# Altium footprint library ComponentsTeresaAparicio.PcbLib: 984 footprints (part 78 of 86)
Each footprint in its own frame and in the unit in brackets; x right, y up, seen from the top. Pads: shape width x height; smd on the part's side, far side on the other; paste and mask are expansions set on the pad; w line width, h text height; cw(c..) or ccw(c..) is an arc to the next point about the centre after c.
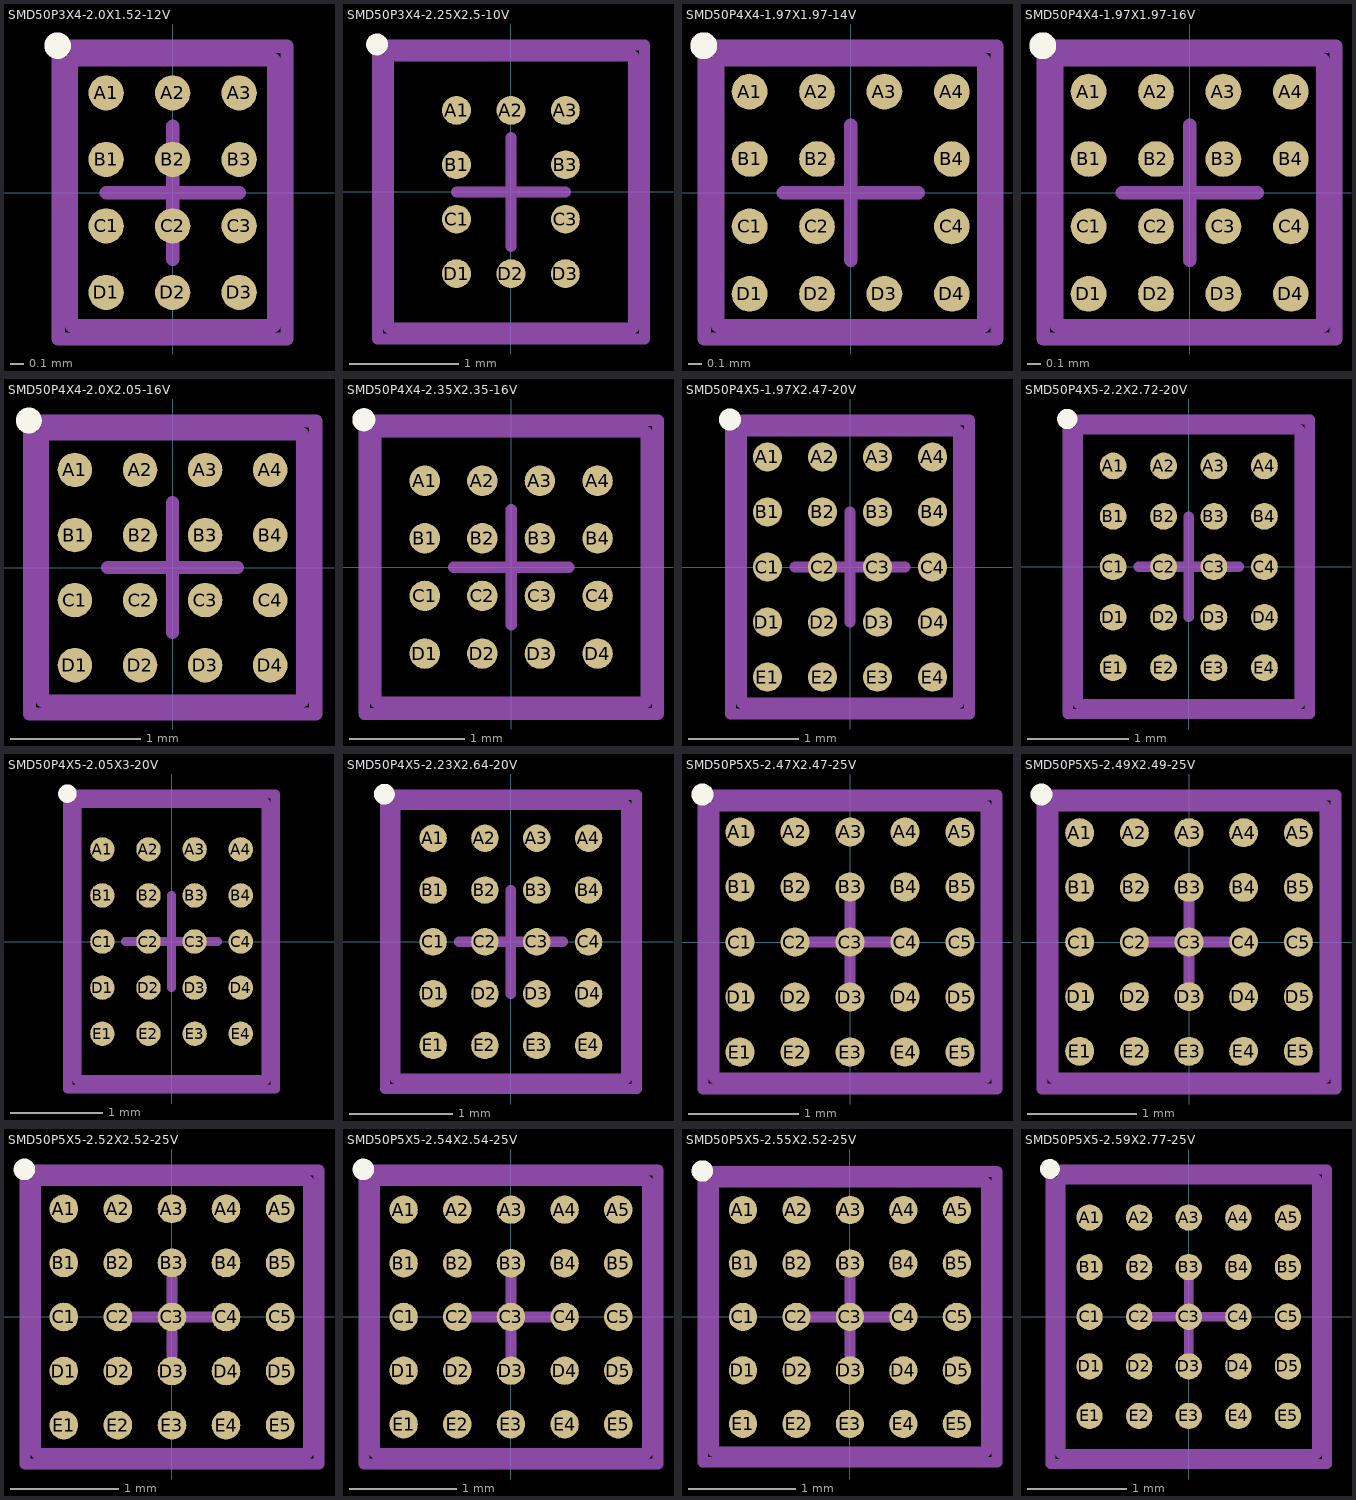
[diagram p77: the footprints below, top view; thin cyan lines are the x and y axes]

## SMD50P3X4-2.0X1.52-12V [mm] "Micro SMD, 12-Leads, Body 1.52x2.0mm, Pitch 0.5mm, NSC Recommended"
height 0.68
pads (12):
  round 0.265 smd paste-0.132 mask+0.05: A1(-0.5,0.75) A2(0,0.75) A3(0.5,0.75) B1(-0.5,0.25) B2(0,0.25) B3(0.5,0.25) C1(-0.5,-0.25) C2(0,-0.25) C3(0.5,-0.25) D1(-0.5,-0.75) D2(0,-0.75) D3(0.5,-0.75)
Top Overlay:
  circle w0.1: c-0.865,1.105 r0.05
Top Paste:
  circle w0.05: c0.075,-0.7 r0.025
  circle w0.05: c-0.075,-0.85 r0.025
  circle w0.05: c-0.075,-0.7 r0.025
  circle w0.05: c0.075,-0.85 r0.025
  circle w0.05: c-0.45,0.175 r0.025
  circle w0.05: c-0.6,0.325 r0.025
  circle w0.05: c-0.6,0.175 r0.025
  circle w0.05: c-0.45,0.325 r0.025
  circle w0.05: c-0.45,-0.325 r0.025
  circle w0.05: c-0.6,-0.175 r0.025
  circle w0.05: c-0.6,-0.325 r0.025
  circle w0.05: c-0.45,-0.175 r0.025
  circle w0.05: c0.075,0.7 r0.025
  circle w0.05: c-0.075,0.85 r0.025
  circle w0.05: c-0.075,0.7 r0.025
  circle w0.05: c0.075,0.85 r0.025
  circle w0.05: c0.6,-0.325 r0.025
  circle w0.05: c0.45,-0.175 r0.025
  circle w0.05: c0.45,-0.325 r0.025
  circle w0.05: c0.6,-0.175 r0.025
  circle w0.05: c0.6,0.175 r0.025
  circle w0.05: c0.45,0.325 r0.025
  circle w0.05: c0.45,0.175 r0.025
  circle w0.05: c0.6,0.325 r0.025
  circle w0.05: c0.075,0.325 r0.025
  circle w0.05: c-0.075,0.175 r0.025
  circle w0.05: c-0.075,0.325 r0.025
  circle w0.05: c0.075,0.175 r0.025
  circle w0.05: c0.075,-0.175 r0.025
  circle w0.05: c-0.075,-0.325 r0.025
  circle w0.05: c-0.075,-0.175 r0.025
  circle w0.05: c0.075,-0.325 r0.025
  circle w0.05: c-0.45,0.7 r0.025
  circle w0.05: c-0.6,0.85 r0.025
  circle w0.05: c-0.6,0.7 r0.025
  circle w0.05: c-0.45,0.85 r0.025
  circle w0.05: c0.6,0.7 r0.025
  circle w0.05: c0.45,0.85 r0.025
  circle w0.05: c0.45,0.7 r0.025
  circle w0.05: c0.6,0.85 r0.025
  circle w0.05: c-0.45,-0.7 r0.025
  circle w0.05: c-0.6,-0.85 r0.025
  circle w0.05: c-0.6,-0.7 r0.025
  circle w0.05: c-0.45,-0.85 r0.025
  circle w0.05: c0.6,-0.7 r0.025
  circle w0.05: c0.45,-0.85 r0.025
  circle w0.05: c0.45,-0.7 r0.025
  circle w0.05: c0.6,-0.85 r0.025
  rectangle: -0.075,-0.9 0.075,-0.85
  region: -0.125,-0.7 -0.125,-0.85 -0.075,-0.85 -0.075,-0.7
  region: 0.075,-0.65 -0.075,-0.65 -0.075,-0.7 0.075,-0.7
  region: 0.125,-0.85 0.125,-0.7 0.075,-0.7 0.075,-0.85
  region: -0.075,-0.7 -0.075,-0.85 0.075,-0.85 0.075,-0.7
  region: -0.6,0.325 -0.6,0.175 -0.45,0.175 -0.45,0.325
  region: -0.4,0.175 -0.4,0.325 -0.45,0.325 -0.45,0.175
  region: -0.45,0.375 -0.6,0.375 -0.6,0.325 -0.45,0.325
  region: -0.65,0.325 -0.65,0.175 -0.6,0.175 -0.6,0.325
  rectangle: -0.6,0.125 -0.45,0.175
  region: -0.6,-0.175 -0.6,-0.325 -0.45,-0.325 -0.45,-0.175
  region: -0.4,-0.325 -0.4,-0.175 -0.45,-0.175 -0.45,-0.325
  region: -0.45,-0.125 -0.6,-0.125 -0.6,-0.175 -0.45,-0.175
  region: -0.65,-0.175 -0.65,-0.325 -0.6,-0.325 -0.6,-0.175
  rectangle: -0.6,-0.375 -0.45,-0.325
  region: -0.075,0.85 -0.075,0.7 0.075,0.7 0.075,0.85
  region: 0.125,0.7 0.125,0.85 0.075,0.85 0.075,0.7
  region: 0.075,0.9 -0.075,0.9 -0.075,0.85 0.075,0.85
  region: -0.125,0.85 -0.125,0.7 -0.075,0.7 -0.075,0.85
  rectangle: -0.075,0.65 0.075,0.7
  region: 0.45,-0.175 0.45,-0.325 0.6,-0.325 0.6,-0.175
  region: 0.65,-0.325 0.65,-0.175 0.6,-0.175 0.6,-0.325
  region: 0.6,-0.125 0.45,-0.125 0.45,-0.175 0.6,-0.175
  region: 0.4,-0.175 0.4,-0.325 0.45,-0.325 0.45,-0.175
  rectangle: 0.45,-0.375 0.6,-0.325
  region: 0.45,0.325 0.45,0.175 0.6,0.175 0.6,0.325
  region: 0.65,0.175 0.65,0.325 0.6,0.325 0.6,0.175
  region: 0.6,0.375 0.45,0.375 0.45,0.325 0.6,0.325
  region: 0.4,0.325 0.4,0.175 0.45,0.175 0.45,0.325
  rectangle: 0.45,0.125 0.6,0.175
  rectangle: -0.075,0.125 0.075,0.175
  region: -0.125,0.325 -0.125,0.175 -0.075,0.175 -0.075,0.325
  region: 0.075,0.375 -0.075,0.375 -0.075,0.325 0.075,0.325
  region: 0.125,0.175 0.125,0.325 0.075,0.325 0.075,0.175
  region: -0.075,0.325 -0.075,0.175 0.075,0.175 0.075,0.325
  rectangle: -0.075,-0.375 0.075,-0.325
  region: -0.125,-0.175 -0.125,-0.325 -0.075,-0.325 -0.075,-0.175
  region: 0.075,-0.125 -0.075,-0.125 -0.075,-0.175 0.075,-0.175
  region: 0.125,-0.325 0.125,-0.175 0.075,-0.175 0.075,-0.325
  region: -0.075,-0.175 -0.075,-0.325 0.075,-0.325 0.075,-0.175
  region: -0.6,0.85 -0.6,0.7 -0.45,0.7 -0.45,0.85
  region: -0.4,0.7 -0.4,0.85 -0.45,0.85 -0.45,0.7
  region: -0.45,0.9 -0.6,0.9 -0.6,0.85 -0.45,0.85
  region: -0.65,0.85 -0.65,0.7 -0.6,0.7 -0.6,0.85
  rectangle: -0.6,0.65 -0.45,0.7
  region: 0.45,0.85 0.45,0.7 0.6,0.7 0.6,0.85
  region: 0.65,0.7 0.65,0.85 0.6,0.85 0.6,0.7
  region: 0.6,0.9 0.45,0.9 0.45,0.85 0.6,0.85
  region: 0.4,0.85 0.4,0.7 0.45,0.7 0.45,0.85
  rectangle: 0.45,0.65 0.6,0.7
  rectangle: -0.6,-0.9 -0.45,-0.85
  region: -0.65,-0.7 -0.65,-0.85 -0.6,-0.85 -0.6,-0.7
  region: -0.45,-0.65 -0.6,-0.65 -0.6,-0.7 -0.45,-0.7
  region: -0.4,-0.85 -0.4,-0.7 -0.45,-0.7 -0.45,-0.85
  region: -0.6,-0.7 -0.6,-0.85 -0.45,-0.85 -0.45,-0.7
  rectangle: 0.45,-0.9 0.6,-0.85
  region: 0.4,-0.7 0.4,-0.85 0.45,-0.85 0.45,-0.7
  region: 0.6,-0.65 0.45,-0.65 0.45,-0.7 0.6,-0.7
  region: 0.65,-0.85 0.65,-0.7 0.6,-0.7 0.6,-0.85
  region: 0.45,-0.7 0.45,-0.85 0.6,-0.85 0.6,-0.7
Mechanical 13:
  lines w0.1: -0.76,-1 -0.76,1 0.76,1 0.76,-1 -0.76,-1
Mechanical 15:
  lines w0.1: -0.5,0 0.5,0 ; 0,-0.5 0,0.5 ; -0.86,-1.1 -0.86,1.1 0.86,1.1 0.86,-1.1 -0.86,-1.1
3D body: height 0.68, standoff 0, extent -0.759,-0.999 0.759,1

## SMD50P3X4-2.25X2.5-10V [mm] "Micro SMD, 10-Leads, Body 2.5x2.25mm, Pitch 0.5mm, NSC Recommended"
height 0.68
pads (10):
  round 0.265 smd paste-0.132 mask+0.05: A1(-0.5,0.75) A2(0,0.75) A3(0.5,0.75) B1(-0.5,0.25) B3(0.5,0.25) C1(-0.5,-0.25) C3(0.5,-0.25) D1(-0.5,-0.75) D2(0,-0.75) D3(0.5,-0.75)
Top Overlay:
  circle w0.1: c-1.23,1.355 r0.05
Top Paste:
  circle w0.05: c0.45,-0.7 r0.025
  circle w0.05: c0.6,-0.85 r0.025
  circle w0.05: c0.6,-0.7 r0.025
  circle w0.05: c0.45,-0.85 r0.025
  circle w0.05: c-0.075,-0.7 r0.025
  circle w0.05: c0.075,-0.85 r0.025
  circle w0.05: c0.075,-0.7 r0.025
  circle w0.05: c-0.075,-0.85 r0.025
  circle w0.05: c-0.6,-0.7 r0.025
  circle w0.05: c-0.45,-0.85 r0.025
  circle w0.05: c-0.45,-0.7 r0.025
  circle w0.05: c-0.6,-0.85 r0.025
  circle w0.05: c0.45,-0.175 r0.025
  circle w0.05: c0.6,-0.325 r0.025
  circle w0.05: c0.6,-0.175 r0.025
  circle w0.05: c0.45,-0.325 r0.025
  circle w0.05: c-0.6,-0.175 r0.025
  circle w0.05: c-0.45,-0.325 r0.025
  circle w0.05: c-0.45,-0.175 r0.025
  circle w0.05: c-0.6,-0.325 r0.025
  circle w0.05: c0.45,0.325 r0.025
  circle w0.05: c0.6,0.175 r0.025
  circle w0.05: c0.6,0.325 r0.025
  circle w0.05: c0.45,0.175 r0.025
  circle w0.05: c-0.6,0.325 r0.025
  circle w0.05: c-0.45,0.175 r0.025
  circle w0.05: c-0.45,0.325 r0.025
  circle w0.05: c-0.6,0.175 r0.025
  circle w0.05: c0.45,0.85 r0.025
  circle w0.05: c0.6,0.7 r0.025
  circle w0.05: c0.6,0.85 r0.025
  circle w0.05: c0.45,0.7 r0.025
  circle w0.05: c-0.075,0.85 r0.025
  circle w0.05: c0.075,0.7 r0.025
  circle w0.05: c0.075,0.85 r0.025
  circle w0.05: c-0.075,0.7 r0.025
  circle w0.05: c-0.6,0.85 r0.025
  circle w0.05: c-0.45,0.7 r0.025
  circle w0.05: c-0.45,0.85 r0.025
  circle w0.05: c-0.6,0.7 r0.025
  region: 0.6,-0.85 0.45,-0.85 0.45,-0.9 0.6,-0.9
  region: 0.6,-0.7 0.6,-0.85 0.65,-0.85 0.65,-0.7
  rectangle: 0.45,-0.7 0.6,-0.65
  region: 0.45,-0.85 0.45,-0.7 0.4,-0.7 0.4,-0.85
  region: 0.45,-0.7 0.45,-0.85 0.6,-0.85 0.6,-0.7
  region: 0.075,-0.85 -0.075,-0.85 -0.075,-0.9 0.075,-0.9
  region: 0.075,-0.7 0.075,-0.85 0.125,-0.85 0.125,-0.7
  rectangle: -0.075,-0.7 0.075,-0.65
  region: -0.075,-0.85 -0.075,-0.7 -0.125,-0.7 -0.125,-0.85
  region: -0.075,-0.7 -0.075,-0.85 0.075,-0.85 0.075,-0.7
  region: -0.45,-0.85 -0.6,-0.85 -0.6,-0.9 -0.45,-0.9
  region: -0.45,-0.7 -0.45,-0.85 -0.4,-0.85 -0.4,-0.7
  rectangle: -0.6,-0.7 -0.45,-0.65
  region: -0.6,-0.85 -0.6,-0.7 -0.65,-0.7 -0.65,-0.85
  region: -0.6,-0.7 -0.6,-0.85 -0.45,-0.85 -0.45,-0.7
  region: 0.6,-0.325 0.45,-0.325 0.45,-0.375 0.6,-0.375
  region: 0.6,-0.175 0.6,-0.325 0.65,-0.325 0.65,-0.175
  rectangle: 0.45,-0.175 0.6,-0.125
  region: 0.45,-0.325 0.45,-0.175 0.4,-0.175 0.4,-0.325
  region: 0.45,-0.175 0.45,-0.325 0.6,-0.325 0.6,-0.175
  region: -0.45,-0.325 -0.6,-0.325 -0.6,-0.375 -0.45,-0.375
  region: -0.45,-0.175 -0.45,-0.325 -0.4,-0.325 -0.4,-0.175
  rectangle: -0.6,-0.175 -0.45,-0.125
  region: -0.6,-0.325 -0.6,-0.175 -0.65,-0.175 -0.65,-0.325
  region: -0.6,-0.175 -0.6,-0.325 -0.45,-0.325 -0.45,-0.175
  region: 0.6,0.175 0.45,0.175 0.45,0.125 0.6,0.125
  region: 0.6,0.325 0.6,0.175 0.65,0.175 0.65,0.325
  rectangle: 0.45,0.325 0.6,0.375
  region: 0.45,0.175 0.45,0.325 0.4,0.325 0.4,0.175
  region: 0.45,0.325 0.45,0.175 0.6,0.175 0.6,0.325
  region: -0.45,0.175 -0.6,0.175 -0.6,0.125 -0.45,0.125
  region: -0.45,0.325 -0.45,0.175 -0.4,0.175 -0.4,0.325
  rectangle: -0.6,0.325 -0.45,0.375
  region: -0.6,0.175 -0.6,0.325 -0.65,0.325 -0.65,0.175
  region: -0.6,0.325 -0.6,0.175 -0.45,0.175 -0.45,0.325
  region: 0.6,0.7 0.45,0.7 0.45,0.65 0.6,0.65
  region: 0.6,0.85 0.6,0.7 0.65,0.7 0.65,0.85
  rectangle: 0.45,0.85 0.6,0.9
  region: 0.45,0.7 0.45,0.85 0.4,0.85 0.4,0.7
  region: 0.45,0.85 0.45,0.7 0.6,0.7 0.6,0.85
  region: 0.075,0.7 -0.075,0.7 -0.075,0.65 0.075,0.65
  region: 0.075,0.85 0.075,0.7 0.125,0.7 0.125,0.85
  rectangle: -0.075,0.85 0.075,0.9
  region: -0.075,0.7 -0.075,0.85 -0.125,0.85 -0.125,0.7
  region: -0.075,0.85 -0.075,0.7 0.075,0.7 0.075,0.85
  region: -0.45,0.7 -0.6,0.7 -0.6,0.65 -0.45,0.65
  region: -0.45,0.85 -0.45,0.7 -0.4,0.7 -0.4,0.85
  rectangle: -0.6,0.85 -0.45,0.9
  region: -0.6,0.7 -0.6,0.85 -0.65,0.85 -0.65,0.7
  region: -0.6,0.85 -0.6,0.7 -0.45,0.7 -0.45,0.85
Mechanical 13:
  lines w0.1: -1.125,-1.25 1.125,-1.25 1.125,1.25 -1.125,1.25 -1.125,-1.25
Mechanical 15:
  lines w0.1: -0.5,0 0.5,0 ; 0,-0.5 0,0.5 ; -1.225,-1.35 1.225,-1.35 1.225,1.35 -1.225,1.35 -1.225,-1.35
3D body: height 0.68, standoff 0, extent -1.125,-1.255 1.125,1.255

## SMD50P4X4-1.97X1.97-14V [mm] "Micro SMD, 14-Leads, Body 1.97x1.97mm, Pitch 0.5mm, NSC Recommended"
height 0.68
pads (14):
  round 0.265 smd paste-0.132 mask+0.05: A1(-0.75,0.75) A2(-0.25,0.75) A3(0.25,0.75) A4(0.75,0.75) B1(-0.75,0.25) B2(-0.25,0.25) B4(0.75,0.25) C1(-0.75,-0.25) C2(-0.25,-0.25) C4(0.75,-0.25) D1(-0.75,-0.75) D2(-0.25,-0.75) D3(0.25,-0.75) D4(0.75,-0.75)
Top Overlay:
  circle w0.1: c-1.09,1.09 r0.05
Top Paste:
  circle w0.05: c-0.175,-0.175 r0.025
  circle w0.05: c-0.325,-0.325 r0.025
  circle w0.05: c-0.325,-0.175 r0.025
  circle w0.05: c-0.175,-0.325 r0.025
  circle w0.05: c-0.175,0.325 r0.025
  circle w0.05: c-0.325,0.175 r0.025
  circle w0.05: c-0.325,0.325 r0.025
  circle w0.05: c-0.175,0.175 r0.025
  circle w0.05: c0.325,-0.85 r0.025
  circle w0.05: c0.175,-0.7 r0.025
  circle w0.05: c0.175,-0.85 r0.025
  circle w0.05: c0.325,-0.7 r0.025
  circle w0.05: c-0.175,-0.85 r0.025
  circle w0.05: c-0.325,-0.7 r0.025
  circle w0.05: c-0.325,-0.85 r0.025
  circle w0.05: c-0.175,-0.7 r0.025
  circle w0.05: c-0.85,-0.325 r0.025
  circle w0.05: c-0.7,-0.175 r0.025
  circle w0.05: c-0.85,-0.175 r0.025
  circle w0.05: c-0.7,-0.325 r0.025
  circle w0.05: c-0.85,0.175 r0.025
  circle w0.05: c-0.7,0.325 r0.025
  circle w0.05: c-0.85,0.325 r0.025
  circle w0.05: c-0.7,0.175 r0.025
  circle w0.05: c-0.325,0.85 r0.025
  circle w0.05: c-0.175,0.7 r0.025
  circle w0.05: c-0.175,0.85 r0.025
  circle w0.05: c-0.325,0.7 r0.025
  circle w0.05: c0.175,0.85 r0.025
  circle w0.05: c0.325,0.7 r0.025
  circle w0.05: c0.325,0.85 r0.025
  circle w0.05: c0.175,0.7 r0.025
  circle w0.05: c0.85,0.325 r0.025
  circle w0.05: c0.7,0.175 r0.025
  circle w0.05: c0.85,0.175 r0.025
  circle w0.05: c0.7,0.325 r0.025
  circle w0.05: c0.85,-0.175 r0.025
  circle w0.05: c0.7,-0.325 r0.025
  circle w0.05: c0.85,-0.325 r0.025
  circle w0.05: c0.7,-0.175 r0.025
  circle w0.05: c-0.7,0.7 r0.025
  circle w0.05: c-0.85,0.85 r0.025
  circle w0.05: c-0.7,0.85 r0.025
  circle w0.05: c-0.85,0.7 r0.025
  circle w0.05: c-0.7,-0.7 r0.025
  circle w0.05: c-0.85,-0.85 r0.025
  circle w0.05: c-0.85,-0.7 r0.025
  circle w0.05: c-0.7,-0.85 r0.025
  circle w0.05: c0.7,-0.7 r0.025
  circle w0.05: c0.85,-0.85 r0.025
  circle w0.05: c0.7,-0.85 r0.025
  circle w0.05: c0.85,-0.7 r0.025
  circle w0.05: c0.7,0.7 r0.025
  circle w0.05: c0.85,0.85 r0.025
  circle w0.05: c0.85,0.7 r0.025
  circle w0.05: c0.7,0.85 r0.025
  rectangle: -0.325,-0.375 -0.175,-0.325
  region: -0.375,-0.175 -0.375,-0.325 -0.325,-0.325 -0.325,-0.175
  region: -0.175,-0.125 -0.325,-0.125 -0.325,-0.175 -0.175,-0.175
  region: -0.125,-0.325 -0.125,-0.175 -0.175,-0.175 -0.175,-0.325
  region: -0.325,-0.175 -0.325,-0.325 -0.175,-0.325 -0.175,-0.175
  rectangle: -0.325,0.125 -0.175,0.175
  region: -0.375,0.325 -0.375,0.175 -0.325,0.175 -0.325,0.325
  region: -0.175,0.375 -0.325,0.375 -0.325,0.325 -0.175,0.325
  region: -0.125,0.175 -0.125,0.325 -0.175,0.325 -0.175,0.175
  region: -0.325,0.325 -0.325,0.175 -0.175,0.175 -0.175,0.325
  rectangle: 0.175,-0.7 0.325,-0.65
  region: 0.175,-0.85 0.175,-0.7 0.125,-0.7 0.125,-0.85
  region: 0.325,-0.85 0.175,-0.85 0.175,-0.9 0.325,-0.9
  region: 0.325,-0.7 0.325,-0.85 0.375,-0.85 0.375,-0.7
  region: 0.325,-0.85 0.325,-0.7 0.175,-0.7 0.175,-0.85
  rectangle: -0.325,-0.7 -0.175,-0.65
  region: -0.325,-0.85 -0.325,-0.7 -0.375,-0.7 -0.375,-0.85
  region: -0.175,-0.85 -0.325,-0.85 -0.325,-0.9 -0.175,-0.9
  region: -0.175,-0.7 -0.175,-0.85 -0.125,-0.85 -0.125,-0.7
  region: -0.175,-0.85 -0.175,-0.7 -0.325,-0.7 -0.325,-0.85
  region: -0.7,-0.175 -0.7,-0.325 -0.65,-0.325 -0.65,-0.175
  rectangle: -0.85,-0.175 -0.7,-0.125
  region: -0.85,-0.325 -0.85,-0.175 -0.9,-0.175 -0.9,-0.325
  region: -0.7,-0.325 -0.85,-0.325 -0.85,-0.375 -0.7,-0.375
  rectangle: -0.85,-0.325 -0.7,-0.175
  region: -0.7,0.325 -0.7,0.175 -0.65,0.175 -0.65,0.325
  rectangle: -0.85,0.325 -0.7,0.375
  region: -0.85,0.175 -0.85,0.325 -0.9,0.325 -0.9,0.175
  region: -0.7,0.175 -0.85,0.175 -0.85,0.125 -0.7,0.125
  rectangle: -0.85,0.175 -0.7,0.325
  region: -0.175,0.7 -0.325,0.7 -0.325,0.65 -0.175,0.65
  region: -0.175,0.85 -0.175,0.7 -0.125,0.7 -0.125,0.85
  rectangle: -0.325,0.85 -0.175,0.9
  region: -0.325,0.7 -0.325,0.85 -0.375,0.85 -0.375,0.7
  region: -0.325,0.85 -0.325,0.7 -0.175,0.7 -0.175,0.85
  region: 0.325,0.7 0.175,0.7 0.175,0.65 0.325,0.65
  region: 0.325,0.85 0.325,0.7 0.375,0.7 0.375,0.85
  rectangle: 0.175,0.85 0.325,0.9
  region: 0.175,0.7 0.175,0.85 0.125,0.85 0.125,0.7
  region: 0.175,0.85 0.175,0.7 0.325,0.7 0.325,0.85
  region: 0.7,0.175 0.7,0.325 0.65,0.325 0.65,0.175
  region: 0.85,0.175 0.7,0.175 0.7,0.125 0.85,0.125
  region: 0.85,0.325 0.85,0.175 0.9,0.175 0.9,0.325
  rectangle: 0.7,0.325 0.85,0.375
  region: 0.85,0.325 0.7,0.325 0.7,0.175 0.85,0.175
  region: 0.7,-0.325 0.7,-0.175 0.65,-0.175 0.65,-0.325
  region: 0.85,-0.325 0.7,-0.325 0.7,-0.375 0.85,-0.375
  region: 0.85,-0.175 0.85,-0.325 0.9,-0.325 0.9,-0.175
  rectangle: 0.7,-0.175 0.85,-0.125
  region: 0.85,-0.175 0.7,-0.175 0.7,-0.325 0.85,-0.325
  rectangle: -0.85,0.7 -0.7,0.85
  region: -0.7,0.7 -0.85,0.7 -0.85,0.65 -0.7,0.65
  region: -0.85,0.7 -0.85,0.85 -0.9,0.85 -0.9,0.7
  rectangle: -0.85,0.85 -0.7,0.9
  region: -0.7,0.85 -0.7,0.7 -0.65,0.7 -0.65,0.85
  region: -0.7,-0.85 -0.7,-0.7 -0.85,-0.7 -0.85,-0.85
  region: -0.7,-0.7 -0.7,-0.85 -0.65,-0.85 -0.65,-0.7
  region: -0.7,-0.85 -0.85,-0.85 -0.85,-0.9 -0.7,-0.9
  region: -0.85,-0.85 -0.85,-0.7 -0.9,-0.7 -0.9,-0.85
  rectangle: -0.85,-0.7 -0.7,-0.65
  region: 0.85,-0.7 0.7,-0.7 0.7,-0.85 0.85,-0.85
  rectangle: 0.7,-0.7 0.85,-0.65
  region: 0.85,-0.7 0.85,-0.85 0.9,-0.85 0.9,-0.7
  region: 0.85,-0.85 0.7,-0.85 0.7,-0.9 0.85,-0.9
  region: 0.7,-0.85 0.7,-0.7 0.65,-0.7 0.65,-0.85
  region: 0.7,0.85 0.7,0.7 0.85,0.7 0.85,0.85
  region: 0.7,0.7 0.7,0.85 0.65,0.85 0.65,0.7
  rectangle: 0.7,0.85 0.85,0.9
  region: 0.85,0.85 0.85,0.7 0.9,0.7 0.9,0.85
  region: 0.85,0.7 0.7,0.7 0.7,0.65 0.85,0.65
Mechanical 13:
  lines w0.1: -0.985,-0.985 -0.985,0.985 0.985,0.985 0.985,-0.985 -0.985,-0.985
Mechanical 15:
  lines w0.1: -0.5,0 0.5,0 ; 0,-0.5 0,0.5 ; -1.085,-1.085 -1.085,1.085 1.085,1.085 1.085,-1.085 -1.085,-1.085
3D body: height 0.68, standoff 0, extent -0.984,-0.984 0.984,0.984

## SMD50P4X4-1.97X1.97-16V [mm] "Micro SMD, 16-Leads, Body 1.97x1.97mm, Pitch 0.5mm, NSC Recommended"
height 0.68
pads (16):
  round 0.265 smd paste-0.132 mask+0.05: A1(-0.75,0.75) A2(-0.25,0.75) A3(0.25,0.75) A4(0.75,0.75) B1(-0.75,0.25) B2(-0.25,0.25) B3(0.25,0.25) B4(0.75,0.25) C1(-0.75,-0.25) C2(-0.25,-0.25) C3(0.25,-0.25) C4(0.75,-0.25) D1(-0.75,-0.75) D2(-0.25,-0.75) D3(0.25,-0.75) D4(0.75,-0.75)
Top Overlay:
  circle w0.1: c-1.09,1.09 r0.05
Top Paste:
  circle w0.05: c0.85,-0.7 r0.025
  circle w0.05: c0.7,-0.85 r0.025
  circle w0.05: c0.85,-0.85 r0.025
  circle w0.05: c0.7,-0.7 r0.025
  circle w0.05: c-0.7,-0.85 r0.025
  circle w0.05: c-0.85,-0.7 r0.025
  circle w0.05: c-0.85,-0.85 r0.025
  circle w0.05: c-0.7,-0.7 r0.025
  circle w0.05: c-0.85,0.7 r0.025
  circle w0.05: c-0.7,0.85 r0.025
  circle w0.05: c-0.85,0.85 r0.025
  circle w0.05: c-0.7,0.7 r0.025
  circle w0.05: c0.7,0.85 r0.025
  circle w0.05: c0.85,0.7 r0.025
  circle w0.05: c0.85,0.85 r0.025
  circle w0.05: c0.7,0.7 r0.025
  circle w0.05: c-0.175,-0.7 r0.025
  circle w0.05: c-0.325,-0.85 r0.025
  circle w0.05: c-0.325,-0.7 r0.025
  circle w0.05: c-0.175,-0.85 r0.025
  circle w0.05: c0.325,-0.7 r0.025
  circle w0.05: c0.175,-0.85 r0.025
  circle w0.05: c0.175,-0.7 r0.025
  circle w0.05: c0.325,-0.85 r0.025
  circle w0.05: c0.7,-0.175 r0.025
  circle w0.05: c0.85,-0.325 r0.025
  circle w0.05: c0.7,-0.325 r0.025
  circle w0.05: c0.85,-0.175 r0.025
  circle w0.05: c0.7,0.325 r0.025
  circle w0.05: c0.85,0.175 r0.025
  circle w0.05: c0.7,0.175 r0.025
  circle w0.05: c0.85,0.325 r0.025
  circle w0.05: c0.175,0.7 r0.025
  circle w0.05: c0.325,0.85 r0.025
  circle w0.05: c0.325,0.7 r0.025
  circle w0.05: c0.175,0.85 r0.025
  circle w0.05: c-0.325,0.7 r0.025
  circle w0.05: c-0.175,0.85 r0.025
  circle w0.05: c-0.175,0.7 r0.025
  circle w0.05: c-0.325,0.85 r0.025
  circle w0.05: c-0.7,0.175 r0.025
  circle w0.05: c-0.85,0.325 r0.025
  circle w0.05: c-0.7,0.325 r0.025
  circle w0.05: c-0.85,0.175 r0.025
  circle w0.05: c-0.7,-0.325 r0.025
  circle w0.05: c-0.85,-0.175 r0.025
  circle w0.05: c-0.7,-0.175 r0.025
  circle w0.05: c-0.85,-0.325 r0.025
  circle w0.05: c-0.175,0.175 r0.025
  circle w0.05: c-0.325,0.325 r0.025
  circle w0.05: c-0.325,0.175 r0.025
  circle w0.05: c-0.175,0.325 r0.025
  circle w0.05: c-0.175,-0.325 r0.025
  circle w0.05: c-0.325,-0.175 r0.025
  circle w0.05: c-0.325,-0.325 r0.025
  circle w0.05: c-0.175,-0.175 r0.025
  circle w0.05: c0.325,-0.325 r0.025
  circle w0.05: c0.175,-0.175 r0.025
  circle w0.05: c0.175,-0.325 r0.025
  circle w0.05: c0.325,-0.175 r0.025
  circle w0.05: c0.325,0.175 r0.025
  circle w0.05: c0.175,0.325 r0.025
  circle w0.05: c0.175,0.175 r0.025
  circle w0.05: c0.325,0.325 r0.025
  region: 0.7,-0.85 0.7,-0.7 0.65,-0.7 0.65,-0.85
  region: 0.85,-0.85 0.7,-0.85 0.7,-0.9 0.85,-0.9
  region: 0.85,-0.7 0.85,-0.85 0.9,-0.85 0.9,-0.7
  rectangle: 0.7,-0.7 0.85,-0.65
  region: 0.85,-0.7 0.7,-0.7 0.7,-0.85 0.85,-0.85
  rectangle: -0.85,-0.7 -0.7,-0.65
  region: -0.85,-0.85 -0.85,-0.7 -0.9,-0.7 -0.9,-0.85
  region: -0.7,-0.85 -0.85,-0.85 -0.85,-0.9 -0.7,-0.9
  region: -0.7,-0.7 -0.7,-0.85 -0.65,-0.85 -0.65,-0.7
  region: -0.7,-0.85 -0.7,-0.7 -0.85,-0.7 -0.85,-0.85
  region: -0.7,0.85 -0.7,0.7 -0.65,0.7 -0.65,0.85
  rectangle: -0.85,0.85 -0.7,0.9
  region: -0.85,0.7 -0.85,0.85 -0.9,0.85 -0.9,0.7
  region: -0.7,0.7 -0.85,0.7 -0.85,0.65 -0.7,0.65
  rectangle: -0.85,0.7 -0.7,0.85
  region: 0.85,0.7 0.7,0.7 0.7,0.65 0.85,0.65
  region: 0.85,0.85 0.85,0.7 0.9,0.7 0.9,0.85
  rectangle: 0.7,0.85 0.85,0.9
  region: 0.7,0.7 0.7,0.85 0.65,0.85 0.65,0.7
  region: 0.7,0.85 0.7,0.7 0.85,0.7 0.85,0.85
  region: -0.175,-0.85 -0.175,-0.7 -0.325,-0.7 -0.325,-0.85
  region: -0.175,-0.7 -0.175,-0.85 -0.125,-0.85 -0.125,-0.7
  region: -0.175,-0.85 -0.325,-0.85 -0.325,-0.9 -0.175,-0.9
  region: -0.325,-0.85 -0.325,-0.7 -0.375,-0.7 -0.375,-0.85
  rectangle: -0.325,-0.7 -0.175,-0.65
  region: 0.325,-0.85 0.325,-0.7 0.175,-0.7 0.175,-0.85
  region: 0.325,-0.7 0.325,-0.85 0.375,-0.85 0.375,-0.7
  region: 0.325,-0.85 0.175,-0.85 0.175,-0.9 0.325,-0.9
  region: 0.175,-0.85 0.175,-0.7 0.125,-0.7 0.125,-0.85
  rectangle: 0.175,-0.7 0.325,-0.65
  region: 0.85,-0.175 0.7,-0.175 0.7,-0.325 0.85,-0.325
  rectangle: 0.7,-0.175 0.85,-0.125
  region: 0.85,-0.175 0.85,-0.325 0.9,-0.325 0.9,-0.175
  region: 0.85,-0.325 0.7,-0.325 0.7,-0.375 0.85,-0.375
  region: 0.7,-0.325 0.7,-0.175 0.65,-0.175 0.65,-0.325
  region: 0.85,0.325 0.7,0.325 0.7,0.175 0.85,0.175
  rectangle: 0.7,0.325 0.85,0.375
  region: 0.85,0.325 0.85,0.175 0.9,0.175 0.9,0.325
  region: 0.85,0.175 0.7,0.175 0.7,0.125 0.85,0.125
  region: 0.7,0.175 0.7,0.325 0.65,0.325 0.65,0.175
  region: 0.175,0.85 0.175,0.7 0.325,0.7 0.325,0.85
  region: 0.175,0.7 0.175,0.85 0.125,0.85 0.125,0.7
  rectangle: 0.175,0.85 0.325,0.9
  region: 0.325,0.85 0.325,0.7 0.375,0.7 0.375,0.85
  region: 0.325,0.7 0.175,0.7 0.175,0.65 0.325,0.65
  region: -0.325,0.85 -0.325,0.7 -0.175,0.7 -0.175,0.85
  region: -0.325,0.7 -0.325,0.85 -0.375,0.85 -0.375,0.7
  rectangle: -0.325,0.85 -0.175,0.9
  region: -0.175,0.85 -0.175,0.7 -0.125,0.7 -0.125,0.85
  region: -0.175,0.7 -0.325,0.7 -0.325,0.65 -0.175,0.65
  rectangle: -0.85,0.175 -0.7,0.325
  region: -0.7,0.175 -0.85,0.175 -0.85,0.125 -0.7,0.125
  region: -0.85,0.175 -0.85,0.325 -0.9,0.325 -0.9,0.175
  rectangle: -0.85,0.325 -0.7,0.375
  region: -0.7,0.325 -0.7,0.175 -0.65,0.175 -0.65,0.325
  rectangle: -0.85,-0.325 -0.7,-0.175
  region: -0.7,-0.325 -0.85,-0.325 -0.85,-0.375 -0.7,-0.375
  region: -0.85,-0.325 -0.85,-0.175 -0.9,-0.175 -0.9,-0.325
  rectangle: -0.85,-0.175 -0.7,-0.125
  region: -0.7,-0.175 -0.7,-0.325 -0.65,-0.325 -0.65,-0.175
  region: -0.325,0.325 -0.325,0.175 -0.175,0.175 -0.175,0.325
  region: -0.125,0.175 -0.125,0.325 -0.175,0.325 -0.175,0.175
  region: -0.175,0.375 -0.325,0.375 -0.325,0.325 -0.175,0.325
  region: -0.375,0.325 -0.375,0.175 -0.325,0.175 -0.325,0.325
  rectangle: -0.325,0.125 -0.175,0.175
  region: -0.325,-0.175 -0.325,-0.325 -0.175,-0.325 -0.175,-0.175
  region: -0.125,-0.325 -0.125,-0.175 -0.175,-0.175 -0.175,-0.325
  region: -0.175,-0.125 -0.325,-0.125 -0.325,-0.175 -0.175,-0.175
  region: -0.375,-0.175 -0.375,-0.325 -0.325,-0.325 -0.325,-0.175
  rectangle: -0.325,-0.375 -0.175,-0.325
  region: 0.175,-0.175 0.175,-0.325 0.325,-0.325 0.325,-0.175
  region: 0.375,-0.325 0.375,-0.175 0.325,-0.175 0.325,-0.325
  region: 0.325,-0.125 0.175,-0.125 0.175,-0.175 0.325,-0.175
  region: 0.125,-0.175 0.125,-0.325 0.175,-0.325 0.175,-0.175
  rectangle: 0.175,-0.375 0.325,-0.325
  region: 0.175,0.325 0.175,0.175 0.325,0.175 0.325,0.325
  region: 0.375,0.175 0.375,0.325 0.325,0.325 0.325,0.175
  region: 0.325,0.375 0.175,0.375 0.175,0.325 0.325,0.325
  region: 0.125,0.325 0.125,0.175 0.175,0.175 0.175,0.325
  rectangle: 0.175,0.125 0.325,0.175
Mechanical 13:
  lines w0.1: -0.985,-0.985 -0.985,0.985 0.985,0.985 0.985,-0.985 -0.985,-0.985
Mechanical 15:
  lines w0.1: -0.5,0 0.5,0 ; 0,-0.5 0,0.5 ; -1.085,-1.085 -1.085,1.085 1.085,1.085 1.085,-1.085 -1.085,-1.085
3D body: height 0.68, standoff 0, extent -0.984,-0.984 0.984,0.984

## SMD50P4X4-2.0X2.05-16V [mm] "Micro SMD, 16-Leads, Body 2.05x2.0mm, Pitch 0.5mm, NSC Recommended"
height 0.68
pads (16):
  round 0.265 smd paste-0.132 mask+0.05: A1(-0.75,0.75) A2(-0.25,0.75) A3(0.25,0.75) A4(0.75,0.75) B1(-0.75,0.25) B2(-0.25,0.25) B3(0.25,0.25) B4(0.75,0.25) C1(-0.75,-0.25) C2(-0.25,-0.25) C3(0.25,-0.25) C4(0.75,-0.25) D1(-0.75,-0.75) D2(-0.25,-0.75) D3(0.25,-0.75) D4(0.75,-0.75)
Top Overlay:
  circle w0.1: c-1.105,1.13 r0.05
Top Paste:
  circle w0.05: c-0.7,-0.85 r0.025
  circle w0.05: c-0.85,-0.7 r0.025
  circle w0.05: c-0.85,-0.85 r0.025
  circle w0.05: c-0.7,-0.7 r0.025
  circle w0.05: c-0.85,0.7 r0.025
  circle w0.05: c-0.7,0.85 r0.025
  circle w0.05: c-0.85,0.85 r0.025
  circle w0.05: c-0.7,0.7 r0.025
  circle w0.05: c0.7,0.85 r0.025
  circle w0.05: c0.85,0.7 r0.025
  circle w0.05: c0.85,0.85 r0.025
  circle w0.05: c0.7,0.7 r0.025
  circle w0.05: c0.85,-0.7 r0.025
  circle w0.05: c0.7,-0.85 r0.025
  circle w0.05: c0.85,-0.85 r0.025
  circle w0.05: c0.7,-0.7 r0.025
  circle w0.05: c-0.7,0.175 r0.025
  circle w0.05: c-0.85,0.325 r0.025
  circle w0.05: c-0.7,0.325 r0.025
  circle w0.05: c-0.85,0.175 r0.025
  circle w0.05: c-0.7,-0.325 r0.025
  circle w0.05: c-0.85,-0.175 r0.025
  circle w0.05: c-0.7,-0.175 r0.025
  circle w0.05: c-0.85,-0.325 r0.025
  circle w0.05: c-0.175,-0.7 r0.025
  circle w0.05: c-0.325,-0.85 r0.025
  circle w0.05: c-0.325,-0.7 r0.025
  circle w0.05: c-0.175,-0.85 r0.025
  circle w0.05: c0.325,-0.7 r0.025
  circle w0.05: c0.175,-0.85 r0.025
  circle w0.05: c0.175,-0.7 r0.025
  circle w0.05: c0.325,-0.85 r0.025
  circle w0.05: c0.7,-0.175 r0.025
  circle w0.05: c0.85,-0.325 r0.025
  circle w0.05: c0.7,-0.325 r0.025
  circle w0.05: c0.85,-0.175 r0.025
  circle w0.05: c0.7,0.325 r0.025
  circle w0.05: c0.85,0.175 r0.025
  circle w0.05: c0.7,0.175 r0.025
  circle w0.05: c0.85,0.325 r0.025
  circle w0.05: c0.175,0.7 r0.025
  circle w0.05: c0.325,0.85 r0.025
  circle w0.05: c0.325,0.7 r0.025
  circle w0.05: c0.175,0.85 r0.025
  circle w0.05: c-0.325,0.7 r0.025
  circle w0.05: c-0.175,0.85 r0.025
  circle w0.05: c-0.175,0.7 r0.025
  circle w0.05: c-0.325,0.85 r0.025
  circle w0.05: c-0.175,0.175 r0.025
  circle w0.05: c-0.325,0.325 r0.025
  circle w0.05: c-0.325,0.175 r0.025
  circle w0.05: c-0.175,0.325 r0.025
  circle w0.05: c-0.175,-0.325 r0.025
  circle w0.05: c-0.325,-0.175 r0.025
  circle w0.05: c-0.325,-0.325 r0.025
  circle w0.05: c-0.175,-0.175 r0.025
  circle w0.05: c0.325,-0.325 r0.025
  circle w0.05: c0.175,-0.175 r0.025
  circle w0.05: c0.175,-0.325 r0.025
  circle w0.05: c0.325,-0.175 r0.025
  circle w0.05: c0.325,0.175 r0.025
  circle w0.05: c0.175,0.325 r0.025
  circle w0.05: c0.175,0.175 r0.025
  circle w0.05: c0.325,0.325 r0.025
  rectangle: -0.85,-0.7 -0.7,-0.65
  region: -0.85,-0.85 -0.85,-0.7 -0.9,-0.7 -0.9,-0.85
  region: -0.7,-0.85 -0.85,-0.85 -0.85,-0.9 -0.7,-0.9
  region: -0.7,-0.7 -0.7,-0.85 -0.65,-0.85 -0.65,-0.7
  region: -0.7,-0.85 -0.7,-0.7 -0.85,-0.7 -0.85,-0.85
  region: -0.7,0.85 -0.7,0.7 -0.65,0.7 -0.65,0.85
  rectangle: -0.85,0.85 -0.7,0.9
  region: -0.85,0.7 -0.85,0.85 -0.9,0.85 -0.9,0.7
  region: -0.7,0.7 -0.85,0.7 -0.85,0.65 -0.7,0.65
  rectangle: -0.85,0.7 -0.7,0.85
  region: 0.85,0.7 0.7,0.7 0.7,0.65 0.85,0.65
  region: 0.85,0.85 0.85,0.7 0.9,0.7 0.9,0.85
  rectangle: 0.7,0.85 0.85,0.9
  region: 0.7,0.7 0.7,0.85 0.65,0.85 0.65,0.7
  region: 0.7,0.85 0.7,0.7 0.85,0.7 0.85,0.85
  region: 0.7,-0.85 0.7,-0.7 0.65,-0.7 0.65,-0.85
  region: 0.85,-0.85 0.7,-0.85 0.7,-0.9 0.85,-0.9
  region: 0.85,-0.7 0.85,-0.85 0.9,-0.85 0.9,-0.7
  rectangle: 0.7,-0.7 0.85,-0.65
  region: 0.85,-0.7 0.7,-0.7 0.7,-0.85 0.85,-0.85
  rectangle: -0.85,0.175 -0.7,0.325
  region: -0.7,0.175 -0.85,0.175 -0.85,0.125 -0.7,0.125
  region: -0.85,0.175 -0.85,0.325 -0.9,0.325 -0.9,0.175
  rectangle: -0.85,0.325 -0.7,0.375
  region: -0.7,0.325 -0.7,0.175 -0.65,0.175 -0.65,0.325
  rectangle: -0.85,-0.325 -0.7,-0.175
  region: -0.7,-0.325 -0.85,-0.325 -0.85,-0.375 -0.7,-0.375
  region: -0.85,-0.325 -0.85,-0.175 -0.9,-0.175 -0.9,-0.325
  rectangle: -0.85,-0.175 -0.7,-0.125
  region: -0.7,-0.175 -0.7,-0.325 -0.65,-0.325 -0.65,-0.175
  region: -0.175,-0.85 -0.175,-0.7 -0.325,-0.7 -0.325,-0.85
  region: -0.175,-0.7 -0.175,-0.85 -0.125,-0.85 -0.125,-0.7
  region: -0.175,-0.85 -0.325,-0.85 -0.325,-0.9 -0.175,-0.9
  region: -0.325,-0.85 -0.325,-0.7 -0.375,-0.7 -0.375,-0.85
  rectangle: -0.325,-0.7 -0.175,-0.65
  region: 0.325,-0.85 0.325,-0.7 0.175,-0.7 0.175,-0.85
  region: 0.325,-0.7 0.325,-0.85 0.375,-0.85 0.375,-0.7
  region: 0.325,-0.85 0.175,-0.85 0.175,-0.9 0.325,-0.9
  region: 0.175,-0.85 0.175,-0.7 0.125,-0.7 0.125,-0.85
  rectangle: 0.175,-0.7 0.325,-0.65
  region: 0.85,-0.175 0.7,-0.175 0.7,-0.325 0.85,-0.325
  rectangle: 0.7,-0.175 0.85,-0.125
  region: 0.85,-0.175 0.85,-0.325 0.9,-0.325 0.9,-0.175
  region: 0.85,-0.325 0.7,-0.325 0.7,-0.375 0.85,-0.375
  region: 0.7,-0.325 0.7,-0.175 0.65,-0.175 0.65,-0.325
  region: 0.85,0.325 0.7,0.325 0.7,0.175 0.85,0.175
  rectangle: 0.7,0.325 0.85,0.375
  region: 0.85,0.325 0.85,0.175 0.9,0.175 0.9,0.325
  region: 0.85,0.175 0.7,0.175 0.7,0.125 0.85,0.125
  region: 0.7,0.175 0.7,0.325 0.65,0.325 0.65,0.175
  region: 0.175,0.85 0.175,0.7 0.325,0.7 0.325,0.85
  region: 0.175,0.7 0.175,0.85 0.125,0.85 0.125,0.7
  rectangle: 0.175,0.85 0.325,0.9
  region: 0.325,0.85 0.325,0.7 0.375,0.7 0.375,0.85
  region: 0.325,0.7 0.175,0.7 0.175,0.65 0.325,0.65
  region: -0.325,0.85 -0.325,0.7 -0.175,0.7 -0.175,0.85
  region: -0.325,0.7 -0.325,0.85 -0.375,0.85 -0.375,0.7
  rectangle: -0.325,0.85 -0.175,0.9
  region: -0.175,0.85 -0.175,0.7 -0.125,0.7 -0.125,0.85
  region: -0.175,0.7 -0.325,0.7 -0.325,0.65 -0.175,0.65
  region: -0.325,0.325 -0.325,0.175 -0.175,0.175 -0.175,0.325
  region: -0.125,0.175 -0.125,0.325 -0.175,0.325 -0.175,0.175
  region: -0.175,0.375 -0.325,0.375 -0.325,0.325 -0.175,0.325
  region: -0.375,0.325 -0.375,0.175 -0.325,0.175 -0.325,0.325
  rectangle: -0.325,0.125 -0.175,0.175
  region: -0.325,-0.175 -0.325,-0.325 -0.175,-0.325 -0.175,-0.175
  region: -0.125,-0.325 -0.125,-0.175 -0.175,-0.175 -0.175,-0.325
  region: -0.175,-0.125 -0.325,-0.125 -0.325,-0.175 -0.175,-0.175
  region: -0.375,-0.175 -0.375,-0.325 -0.325,-0.325 -0.325,-0.175
  rectangle: -0.325,-0.375 -0.175,-0.325
  region: 0.175,-0.175 0.175,-0.325 0.325,-0.325 0.325,-0.175
  region: 0.375,-0.325 0.375,-0.175 0.325,-0.175 0.325,-0.325
  region: 0.325,-0.125 0.175,-0.125 0.175,-0.175 0.325,-0.175
  region: 0.125,-0.175 0.125,-0.325 0.175,-0.325 0.175,-0.175
  rectangle: 0.175,-0.375 0.325,-0.325
  region: 0.175,0.325 0.175,0.175 0.325,0.175 0.325,0.325
  region: 0.375,0.175 0.375,0.325 0.325,0.325 0.325,0.175
  region: 0.325,0.375 0.175,0.375 0.175,0.325 0.325,0.325
  region: 0.125,0.325 0.125,0.175 0.175,0.175 0.175,0.325
  rectangle: 0.175,0.125 0.325,0.175
Mechanical 13:
  lines w0.1: -1,-1.025 -1,1.025 1,1.025 1,-1.025 -1,-1.025
Mechanical 15:
  lines w0.1: -0.5,0 0.5,0 ; 0,-0.5 0,0.5 ; -1.1,-1.125 -1.1,1.125 1.1,1.125 1.1,-1.125 -1.1,-1.125
3D body: height 0.68, standoff 0, extent -0.999,-1.024 0.999,1.024

## SMD50P4X4-2.35X2.35-16V [mm] "Micro SMD, 16-Leads, Body 2.35x2.35mm, Pitch 0.5mm, NSC Recommended"
height 0.68
pads (16):
  round 0.265 smd paste-0.132 mask+0.05: A1(-0.75,0.75) A2(-0.25,0.75) A3(0.25,0.75) A4(0.75,0.75) B1(-0.75,0.25) B2(-0.25,0.25) B3(0.25,0.25) B4(0.75,0.25) C1(-0.75,-0.25) C2(-0.25,-0.25) C3(0.25,-0.25) C4(0.75,-0.25) D1(-0.75,-0.75) D2(-0.25,-0.75) D3(0.25,-0.75) D4(0.75,-0.75)
Top Overlay:
  circle w0.1: c-1.28,1.28 r0.05
Top Paste:
  circle w0.05: c0.7,-0.7 r0.025
  circle w0.05: c0.85,-0.85 r0.025
  circle w0.05: c0.85,-0.7 r0.025
  circle w0.05: c0.7,-0.85 r0.025
  circle w0.05: c0.175,-0.7 r0.025
  circle w0.05: c0.325,-0.85 r0.025
  circle w0.05: c0.325,-0.7 r0.025
  circle w0.05: c0.175,-0.85 r0.025
  circle w0.05: c-0.325,-0.7 r0.025
  circle w0.05: c-0.175,-0.85 r0.025
  circle w0.05: c-0.175,-0.7 r0.025
  circle w0.05: c-0.325,-0.85 r0.025
  circle w0.05: c-0.85,-0.7 r0.025
  circle w0.05: c-0.7,-0.85 r0.025
  circle w0.05: c-0.7,-0.7 r0.025
  circle w0.05: c-0.85,-0.85 r0.025
  circle w0.05: c0.7,-0.175 r0.025
  circle w0.05: c0.85,-0.325 r0.025
  circle w0.05: c0.85,-0.175 r0.025
  circle w0.05: c0.7,-0.325 r0.025
  circle w0.05: c0.175,-0.175 r0.025
  circle w0.05: c0.325,-0.325 r0.025
  circle w0.05: c0.325,-0.175 r0.025
  circle w0.05: c0.175,-0.325 r0.025
  circle w0.05: c-0.325,-0.175 r0.025
  circle w0.05: c-0.175,-0.325 r0.025
  circle w0.05: c-0.175,-0.175 r0.025
  circle w0.05: c-0.325,-0.325 r0.025
  circle w0.05: c-0.85,-0.175 r0.025
  circle w0.05: c-0.7,-0.325 r0.025
  circle w0.05: c-0.7,-0.175 r0.025
  circle w0.05: c-0.85,-0.325 r0.025
  circle w0.05: c0.7,0.325 r0.025
  circle w0.05: c0.85,0.175 r0.025
  circle w0.05: c0.85,0.325 r0.025
  circle w0.05: c0.7,0.175 r0.025
  circle w0.05: c0.175,0.325 r0.025
  circle w0.05: c0.325,0.175 r0.025
  circle w0.05: c0.325,0.325 r0.025
  circle w0.05: c0.175,0.175 r0.025
  circle w0.05: c-0.325,0.325 r0.025
  circle w0.05: c-0.175,0.175 r0.025
  circle w0.05: c-0.175,0.325 r0.025
  circle w0.05: c-0.325,0.175 r0.025
  circle w0.05: c-0.85,0.325 r0.025
  circle w0.05: c-0.7,0.175 r0.025
  circle w0.05: c-0.7,0.325 r0.025
  circle w0.05: c-0.85,0.175 r0.025
  circle w0.05: c0.7,0.85 r0.025
  circle w0.05: c0.85,0.7 r0.025
  circle w0.05: c0.85,0.85 r0.025
  circle w0.05: c0.7,0.7 r0.025
  circle w0.05: c0.175,0.85 r0.025
  circle w0.05: c0.325,0.7 r0.025
  circle w0.05: c0.325,0.85 r0.025
  circle w0.05: c0.175,0.7 r0.025
  circle w0.05: c-0.325,0.85 r0.025
  circle w0.05: c-0.175,0.7 r0.025
  circle w0.05: c-0.175,0.85 r0.025
  circle w0.05: c-0.325,0.7 r0.025
  circle w0.05: c-0.85,0.85 r0.025
  circle w0.05: c-0.7,0.7 r0.025
  circle w0.05: c-0.7,0.85 r0.025
  circle w0.05: c-0.85,0.7 r0.025
  region: 0.85,-0.85 0.7,-0.85 0.7,-0.9 0.85,-0.9
  region: 0.85,-0.7 0.85,-0.85 0.9,-0.85 0.9,-0.7
  rectangle: 0.7,-0.7 0.85,-0.65
  region: 0.7,-0.85 0.7,-0.7 0.65,-0.7 0.65,-0.85
  region: 0.7,-0.7 0.7,-0.85 0.85,-0.85 0.85,-0.7
  region: 0.325,-0.85 0.175,-0.85 0.175,-0.9 0.325,-0.9
  region: 0.325,-0.7 0.325,-0.85 0.375,-0.85 0.375,-0.7
  rectangle: 0.175,-0.7 0.325,-0.65
  region: 0.175,-0.85 0.175,-0.7 0.125,-0.7 0.125,-0.85
  region: 0.175,-0.7 0.175,-0.85 0.325,-0.85 0.325,-0.7
  region: -0.175,-0.85 -0.325,-0.85 -0.325,-0.9 -0.175,-0.9
  region: -0.175,-0.7 -0.175,-0.85 -0.125,-0.85 -0.125,-0.7
  rectangle: -0.325,-0.7 -0.175,-0.65
  region: -0.325,-0.85 -0.325,-0.7 -0.375,-0.7 -0.375,-0.85
  region: -0.325,-0.7 -0.325,-0.85 -0.175,-0.85 -0.175,-0.7
  region: -0.7,-0.85 -0.85,-0.85 -0.85,-0.9 -0.7,-0.9
  region: -0.7,-0.7 -0.7,-0.85 -0.65,-0.85 -0.65,-0.7
  rectangle: -0.85,-0.7 -0.7,-0.65
  region: -0.85,-0.85 -0.85,-0.7 -0.9,-0.7 -0.9,-0.85
  region: -0.85,-0.7 -0.85,-0.85 -0.7,-0.85 -0.7,-0.7
  region: 0.85,-0.325 0.7,-0.325 0.7,-0.375 0.85,-0.375
  region: 0.85,-0.175 0.85,-0.325 0.9,-0.325 0.9,-0.175
  rectangle: 0.7,-0.175 0.85,-0.125
  region: 0.7,-0.325 0.7,-0.175 0.65,-0.175 0.65,-0.325
  region: 0.7,-0.175 0.7,-0.325 0.85,-0.325 0.85,-0.175
  region: 0.325,-0.325 0.175,-0.325 0.175,-0.375 0.325,-0.375
  region: 0.325,-0.175 0.325,-0.325 0.375,-0.325 0.375,-0.175
  rectangle: 0.175,-0.175 0.325,-0.125
  region: 0.175,-0.325 0.175,-0.175 0.125,-0.175 0.125,-0.325
  region: 0.175,-0.175 0.175,-0.325 0.325,-0.325 0.325,-0.175
  region: -0.175,-0.325 -0.325,-0.325 -0.325,-0.375 -0.175,-0.375
  region: -0.175,-0.175 -0.175,-0.325 -0.125,-0.325 -0.125,-0.175
  rectangle: -0.325,-0.175 -0.175,-0.125
  region: -0.325,-0.325 -0.325,-0.175 -0.375,-0.175 -0.375,-0.325
  region: -0.325,-0.175 -0.325,-0.325 -0.175,-0.325 -0.175,-0.175
  region: -0.7,-0.325 -0.85,-0.325 -0.85,-0.375 -0.7,-0.375
  region: -0.7,-0.175 -0.7,-0.325 -0.65,-0.325 -0.65,-0.175
  rectangle: -0.85,-0.175 -0.7,-0.125
  region: -0.85,-0.325 -0.85,-0.175 -0.9,-0.175 -0.9,-0.325
  region: -0.85,-0.175 -0.85,-0.325 -0.7,-0.325 -0.7,-0.175
  region: 0.85,0.175 0.7,0.175 0.7,0.125 0.85,0.125
  region: 0.85,0.325 0.85,0.175 0.9,0.175 0.9,0.325
  rectangle: 0.7,0.325 0.85,0.375
  region: 0.7,0.175 0.7,0.325 0.65,0.325 0.65,0.175
  region: 0.7,0.325 0.7,0.175 0.85,0.175 0.85,0.325
  region: 0.325,0.175 0.175,0.175 0.175,0.125 0.325,0.125
  region: 0.325,0.325 0.325,0.175 0.375,0.175 0.375,0.325
  rectangle: 0.175,0.325 0.325,0.375
  region: 0.175,0.175 0.175,0.325 0.125,0.325 0.125,0.175
  region: 0.175,0.325 0.175,0.175 0.325,0.175 0.325,0.325
  region: -0.175,0.175 -0.325,0.175 -0.325,0.125 -0.175,0.125
  region: -0.175,0.325 -0.175,0.175 -0.125,0.175 -0.125,0.325
  rectangle: -0.325,0.325 -0.175,0.375
  region: -0.325,0.175 -0.325,0.325 -0.375,0.325 -0.375,0.175
  region: -0.325,0.325 -0.325,0.175 -0.175,0.175 -0.175,0.325
  region: -0.7,0.175 -0.85,0.175 -0.85,0.125 -0.7,0.125
  region: -0.7,0.325 -0.7,0.175 -0.65,0.175 -0.65,0.325
  rectangle: -0.85,0.325 -0.7,0.375
  region: -0.85,0.175 -0.85,0.325 -0.9,0.325 -0.9,0.175
  region: -0.85,0.325 -0.85,0.175 -0.7,0.175 -0.7,0.325
  region: 0.85,0.7 0.7,0.7 0.7,0.65 0.85,0.65
  region: 0.85,0.85 0.85,0.7 0.9,0.7 0.9,0.85
  rectangle: 0.7,0.85 0.85,0.9
  region: 0.7,0.7 0.7,0.85 0.65,0.85 0.65,0.7
  region: 0.7,0.85 0.7,0.7 0.85,0.7 0.85,0.85
  region: 0.325,0.7 0.175,0.7 0.175,0.65 0.325,0.65
  region: 0.325,0.85 0.325,0.7 0.375,0.7 0.375,0.85
  rectangle: 0.175,0.85 0.325,0.9
  region: 0.175,0.7 0.175,0.85 0.125,0.85 0.125,0.7
  region: 0.175,0.85 0.175,0.7 0.325,0.7 0.325,0.85
  region: -0.175,0.7 -0.325,0.7 -0.325,0.65 -0.175,0.65
  region: -0.175,0.85 -0.175,0.7 -0.125,0.7 -0.125,0.85
  rectangle: -0.325,0.85 -0.175,0.9
  region: -0.325,0.7 -0.325,0.85 -0.375,0.85 -0.375,0.7
  region: -0.325,0.85 -0.325,0.7 -0.175,0.7 -0.175,0.85
  region: -0.7,0.7 -0.85,0.7 -0.85,0.65 -0.7,0.65
  region: -0.7,0.85 -0.7,0.7 -0.65,0.7 -0.65,0.85
  rectangle: -0.85,0.85 -0.7,0.9
  region: -0.85,0.7 -0.85,0.85 -0.9,0.85 -0.9,0.7
  region: -0.85,0.85 -0.85,0.7 -0.7,0.7 -0.7,0.85
Mechanical 13:
  lines w0.1: -1.175,-1.175 1.175,-1.175 1.175,1.175 -1.175,1.175 -1.175,-1.175
Mechanical 15:
  lines w0.1: -0.5,0 0.5,0 ; 0,-0.5 0,0.5 ; -1.275,-1.275 1.275,-1.275 1.275,1.275 -1.275,1.275 -1.275,-1.275
3D body: height 0.68, standoff 0, extent -1.175,-1.175 1.175,1.175

## SMD50P4X5-1.97X2.47-20V [mm] "Micro SMD, 20-Leads, Body 2.47x1.97mm, Pitch 0.5mm, NSC Recommended"
height 0.68
pads (20):
  round 0.265 smd paste-0.132 mask+0.05: A1(-0.75,1) A2(-0.25,1) A3(0.25,1) A4(0.75,1) B1(-0.75,0.5) B2(-0.25,0.5) B3(0.25,0.5) B4(0.75,0.5) C1(-0.75,0) C2(-0.25,0) C3(0.25,0) C4(0.75,0) D1(-0.75,-0.5) D2(-0.25,-0.5) D3(0.25,-0.5) D4(0.75,-0.5) E1(-0.75,-1) E2(-0.25,-1) E3(0.25,-1) E4(0.75,-1)
Top Overlay:
  circle w0.1: c-1.09,1.34 r0.05
Top Paste:
  drawing of 180 lines, arcs and shapes, not listed
Mechanical 13:
  lines w0.1: -0.985,-1.235 -0.985,1.235 0.985,1.235 0.985,-1.235 -0.985,-1.235
Mechanical 15:
  lines w0.1: -0.5,0 0.5,0 ; 0,-0.5 0,0.5 ; -1.085,-1.335 -1.085,1.335 1.085,1.335 1.085,-1.335 -1.085,-1.335
3D body: height 0.68, standoff 0, extent -0.984,-1.234 0.984,1.234

## SMD50P4X5-2.2X2.72-20V [mm] "Micro SMD, 20-Leads, Body 2.72x2.2mm, Pitch 0.5mm, NSC Recommended"
height 0.68
pads (20):
  round 0.265 smd paste-0.132 mask+0.05: A1(-0.75,1) A2(-0.25,1) A3(0.25,1) A4(0.75,1) B1(-0.75,0.5) B2(-0.25,0.5) B3(0.25,0.5) B4(0.75,0.5) C1(-0.75,0) C2(-0.25,0) C3(0.25,0) C4(0.75,0) D1(-0.75,-0.5) D2(-0.25,-0.5) D3(0.25,-0.5) D4(0.75,-0.5) E1(-0.75,-1) E2(-0.25,-1) E3(0.25,-1) E4(0.75,-1)
Top Overlay:
  circle w0.1: c-1.205,1.465 r0.05
Top Paste:
  drawing of 180 lines, arcs and shapes, not listed
Mechanical 13:
  lines w0.1: -1.1,-1.36 -1.1,1.36 1.1,1.36 1.1,-1.36 -1.1,-1.36
Mechanical 15:
  lines w0.1: -0.5,0 0.5,0 ; 0,-0.5 0,0.5 ; -1.2,-1.46 -1.2,1.46 1.2,1.46 1.2,-1.46 -1.2,-1.46
3D body: height 0.68, standoff 0, extent -1.099,-1.359 1.099,1.359

## SMD50P4X5-2.05X3-20V [mm] "Micro SMD, 20-Leads, Body 3x2.05mm, Pitch 0.5mm, NSC Recommended"
height 0.68
pads (20):
  round 0.265 smd paste-0.132 mask+0.05: A1(-0.75,1) A2(-0.25,1) A3(0.25,1) A4(0.75,1) B1(-0.75,0.5) B2(-0.25,0.5) B3(0.25,0.5) B4(0.75,0.5) C1(-0.75,0) C2(-0.25,0) C3(0.25,0) C4(0.75,0) D1(-0.75,-0.5) D2(-0.25,-0.5) D3(0.25,-0.5) D4(0.75,-0.5) E1(-0.75,-1) E2(-0.25,-1) E3(0.25,-1) E4(0.75,-1)
Top Overlay:
  circle w0.1: c-1.13,1.605 r0.05
Top Paste:
  drawing of 180 lines, arcs and shapes, not listed
Mechanical 13:
  lines w0.1: -1.025,-1.5 1.025,-1.5 1.025,1.5 -1.025,1.5 -1.025,-1.5
Mechanical 15:
  lines w0.1: -0.5,0 0.5,0 ; 0,-0.5 0,0.5 ; -1.125,-1.6 1.125,-1.6 1.125,1.6 -1.125,1.6 -1.125,-1.6
3D body: height 0.68, standoff 0, extent -1.025,-1.5 1.025,1.5

## SMD50P4X5-2.23X2.64-20V [mm] "Micro SMD, 20-Leads, Body 2.64x2.23mm, Pitch 0.5mm, NSC Recommended"
height 0.68
pads (20):
  round 0.265 smd paste-0.132 mask+0.05: A1(-0.75,1) A2(-0.25,1) A3(0.25,1) A4(0.75,1) B1(-0.75,0.5) B2(-0.25,0.5) B3(0.25,0.5) B4(0.75,0.5) C1(-0.75,0) C2(-0.25,0) C3(0.25,0) C4(0.75,0) D1(-0.75,-0.5) D2(-0.25,-0.5) D3(0.25,-0.5) D4(0.75,-0.5) E1(-0.75,-1) E2(-0.25,-1) E3(0.25,-1) E4(0.75,-1)
Top Overlay:
  circle w0.1: c-1.22,1.425 r0.05
Top Paste:
  drawing of 180 lines, arcs and shapes, not listed
Mechanical 13:
  lines w0.1: -1.115,-1.32 1.115,-1.32 1.115,1.32 -1.115,1.32 -1.115,-1.32
Mechanical 15:
  lines w0.1: -0.5,0 0.5,0 ; 0,-0.5 0,0.5 ; -1.215,-1.42 1.215,-1.42 1.215,1.42 -1.215,1.42 -1.215,-1.42
3D body: height 0.68, standoff 0, extent -1.115,-1.325 1.115,1.325

## SMD50P5X5-2.47X2.47-25V [mm] "Micro SMD, 25-Leads, Body 2.47x2.47mm, Pitch 0.5mm, NSC Recommended"
height 0.68
pads (25):
  round 0.265 smd paste-0.132 mask+0.05: A1(-1,1) A2(-0.5,1) A3(0,1) A4(0.5,1) A5(1,1) B1(-1,0.5) B2(-0.5,0.5) B3(0,0.5) B4(0.5,0.5) B5(1,0.5) C1(-1,0) C2(-0.5,0) C3(0,0) C4(0.5,0) C5(1,0) D1(-1,-0.5) D2(-0.5,-0.5) D3(0,-0.5) D4(0.5,-0.5) D5(1,-0.5) E1(-1,-1) E2(-0.5,-1) E3(0,-1) E4(0.5,-1) E5(1,-1)
Top Overlay:
  circle w0.1: c-1.34,1.34 r0.05
Top Paste:
  drawing of 225 lines, arcs and shapes, not listed
Mechanical 13:
  lines w0.1: -1.235,-1.235 -1.235,1.235 1.235,1.235 1.235,-1.235 -1.235,-1.235
Mechanical 15:
  lines w0.1: -0.5,0 0.5,0 ; 0,-0.5 0,0.5 ; -1.335,-1.335 -1.335,1.335 1.335,1.335 1.335,-1.335 -1.335,-1.335
3D body: height 0.68, standoff 0, extent -1.235,-1.235 1.235,1.235

## SMD50P5X5-2.49X2.49-25V [mm] "Micro SMD, 25-Leads, Body 2.49x2.49mm, Pitch 0.5mm, NSC Recommended"
height 0.68
pads (25):
  round 0.265 smd paste-0.132 mask+0.05: A1(-1,1) A2(-0.5,1) A3(0,1) A4(0.5,1) A5(1,1) B1(-1,0.5) B2(-0.5,0.5) B3(0,0.5) B4(0.5,0.5) B5(1,0.5) C1(-1,0) C2(-0.5,0) C3(0,0) C4(0.5,0) C5(1,0) D1(-1,-0.5) D2(-0.5,-0.5) D3(0,-0.5) D4(0.5,-0.5) D5(1,-0.5) E1(-1,-1) E2(-0.5,-1) E3(0,-1) E4(0.5,-1) E5(1,-1)
Top Overlay:
  circle w0.1: c-1.35,1.35 r0.05
Top Paste:
  drawing of 225 lines, arcs and shapes, not listed
Mechanical 13:
  lines w0.1: -1.245,-1.245 1.245,-1.245 1.245,1.245 -1.245,1.245 -1.245,-1.245
Mechanical 15:
  lines w0.1: -0.5,0 0.5,0 ; 0,-0.5 0,0.5 ; -1.345,-1.345 1.345,-1.345 1.345,1.345 -1.345,1.345 -1.345,-1.345
3D body: height 0.68, standoff 0, extent -1.244,-1.244 1.244,1.244

## SMD50P5X5-2.52X2.52-25V [mm] "Micro SMD, 25-Leads, Body 2.52x2.52mm, Pitch 0.5mm, NSC Recommended"
height 0.68
pads (25):
  round 0.265 smd paste-0.132 mask+0.05: A1(-1,1) A2(-0.5,1) A3(0,1) A4(0.5,1) A5(1,1) B1(-1,0.5) B2(-0.5,0.5) B3(0,0.5) B4(0.5,0.5) B5(1,0.5) C1(-1,0) C2(-0.5,0) C3(0,0) C4(0.5,0) C5(1,0) D1(-1,-0.5) D2(-0.5,-0.5) D3(0,-0.5) D4(0.5,-0.5) D5(1,-0.5) E1(-1,-1) E2(-0.5,-1) E3(0,-1) E4(0.5,-1) E5(1,-1)
Top Overlay:
  circle w0.1: c-1.365,1.365 r0.05
Top Paste:
  drawing of 225 lines, arcs and shapes, not listed
Mechanical 13:
  lines w0.1: -1.26,-1.26 1.26,-1.26 1.26,1.26 -1.26,1.26 -1.26,-1.26
Mechanical 15:
  lines w0.1: -0.5,0 0.5,0 ; 0,-0.5 0,0.5 ; -1.36,-1.36 1.36,-1.36 1.36,1.36 -1.36,1.36 -1.36,-1.36
3D body: height 0.68, standoff 0, extent -1.259,-1.259 1.259,1.259

## SMD50P5X5-2.54X2.54-25V [mm] "Micro SMD, 25-Leads, Body 2.54x2.54mm, Pitch 0.5mm, NSC Recommended"
height 0.68
pads (25):
  round 0.265 smd paste-0.132 mask+0.05: A1(-1,1) A2(-0.5,1) A3(0,1) A4(0.5,1) A5(1,1) B1(-1,0.5) B2(-0.5,0.5) B3(0,0.5) B4(0.5,0.5) B5(1,0.5) C1(-1,0) C2(-0.5,0) C3(0,0) C4(0.5,0) C5(1,0) D1(-1,-0.5) D2(-0.5,-0.5) D3(0,-0.5) D4(0.5,-0.5) D5(1,-0.5) E1(-1,-1) E2(-0.5,-1) E3(0,-1) E4(0.5,-1) E5(1,-1)
Top Overlay:
  circle w0.1: c-1.375,1.375 r0.05
Top Paste:
  drawing of 225 lines, arcs and shapes, not listed
Mechanical 13:
  lines w0.1: -1.27,-1.27 1.27,-1.27 1.27,1.27 -1.27,1.27 -1.27,-1.27
Mechanical 15:
  lines w0.1: -0.5,0 0.5,0 ; 0,-0.5 0,0.5 ; -1.37,-1.37 1.37,-1.37 1.37,1.37 -1.37,1.37 -1.37,-1.37
3D body: height 0.68, standoff 0, extent -1.275,-1.275 1.275,1.275

## SMD50P5X5-2.55X2.52-25V [mm] "Micro SMD, 25-Leads, Body 2.52x2.55mm, Pitch 0.5mm, NSC Recommended"
height 0.68
pads (25):
  round 0.265 smd paste-0.132 mask+0.05: A1(-1,1) A2(-0.5,1) A3(0,1) A4(0.5,1) A5(1,1) B1(-1,0.5) B2(-0.5,0.5) B3(0,0.5) B4(0.5,0.5) B5(1,0.5) C1(-1,0) C2(-0.5,0) C3(0,0) C4(0.5,0) C5(1,0) D1(-1,-0.5) D2(-0.5,-0.5) D3(0,-0.5) D4(0.5,-0.5) D5(1,-0.5) E1(-1,-1) E2(-0.5,-1) E3(0,-1) E4(0.5,-1) E5(1,-1)
Top Overlay:
  circle w0.1: c-1.38,1.365 r0.05
Top Paste:
  drawing of 225 lines, arcs and shapes, not listed
Mechanical 13:
  lines w0.1: -1.275,-1.26 -1.275,1.26 1.275,1.26 1.275,-1.26 -1.275,-1.26
Mechanical 15:
  lines w0.1: -0.5,0 0.5,0 ; 0,-0.5 0,0.5 ; -1.375,-1.36 -1.375,1.36 1.375,1.36 1.375,-1.36 -1.375,-1.36
3D body: height 0.68, standoff 0, extent -1.274,-1.259 1.274,1.259

## SMD50P5X5-2.59X2.77-25V [mm] "Micro SMD, 25-Leads, Body 2.77x2.59mm, Pitch 0.5mm, NSC Recommended"
height 0.68
pads (25):
  round 0.265 smd paste-0.132 mask+0.05: A1(-1,1) A2(-0.5,1) A3(0,1) A4(0.5,1) A5(1,1) B1(-1,0.5) B2(-0.5,0.5) B3(0,0.5) B4(0.5,0.5) B5(1,0.5) C1(-1,0) C2(-0.5,0) C3(0,0) C4(0.5,0) C5(1,0) D1(-1,-0.5) D2(-0.5,-0.5) D3(0,-0.5) D4(0.5,-0.5) D5(1,-0.5) E1(-1,-1) E2(-0.5,-1) E3(0,-1) E4(0.5,-1) E5(1,-1)
Top Overlay:
  circle w0.1: c-1.4,1.49 r0.05
Top Paste:
  drawing of 225 lines, arcs and shapes, not listed
Mechanical 13:
  lines w0.1: -1.295,-1.385 -1.295,1.385 1.295,1.385 1.295,-1.385 -1.295,-1.385
Mechanical 15:
  lines w0.1: -0.5,0 0.5,0 ; 0,-0.5 0,0.5 ; -1.395,-1.485 -1.395,1.485 1.395,1.485 1.395,-1.485 -1.395,-1.485
3D body: height 0.68, standoff 0, extent -1.3,-1.385 1.3,1.385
